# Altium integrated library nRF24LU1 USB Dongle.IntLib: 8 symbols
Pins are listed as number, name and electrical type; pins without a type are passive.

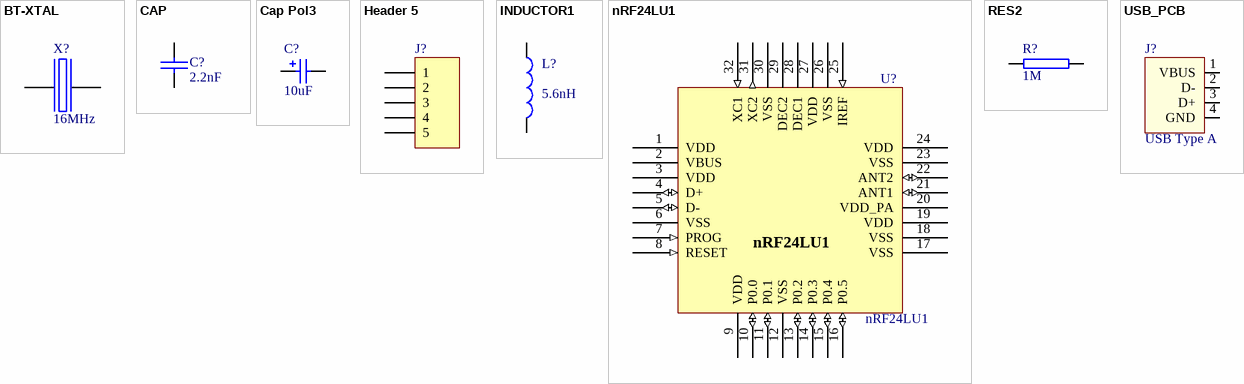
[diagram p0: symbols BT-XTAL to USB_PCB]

## BT-XTAL
designator X?, comment value 16MHz  (hidden comment: FA-20H 16MHz, CL=12pF)
footprint BT-XTAL 2520 (TSX-2520)
pins: 1 inp, 2 GND hidden to GND, 3 out, 4 GND hidden to GND

## CAP
designator C?, comment value 2.2nF  (hidden comment: X7R +/-10%)
Part Field 1: 0402
footprint 0402s
pins: 1, 2

## Cap Pol3
designator C?, comment value 10uF  (hidden comment: X5R +/-10%, 6.3v)
Polarized Capacitor (Surface Mount)
footprint 0603s
footprint C1206 (Chip Capacitor; Body 3.2 x 1.6 mm (LxW typ))
footprint 1825 (Chip Capacitor; Body 4.5 x 6.4 mm (LxW typ))
footprint C2225 (Chip Capacitor; Body 5.6 x 6.4 mm (LxW typ))
footprint 2220 (Chip Capacitor; Body 5.7 x 5.0 mm (LxW typ))
simulation model CAP (Capacitor)
signal-integrity model Cap Pol
pins: 1, 2
1 alternate drawing of the same symbol

## Header 5
designator J?, comment Digikey 455-1791-1-ND  (value not drawn)
Header, 5-Pin; Value: JST BM05B-SRSS-TB
footprint SH-5
signal-integrity model Connector
pins: 1, 2, 3, 4, 5

## INDUCTOR1
designator L?, comment value 5.6nH  (hidden comment: Chip Inductor +/-5%)
Part Field 1: 0402
footprint 0402s
pins: 1, 2

## nRF24LU1
designator U?
2.4GHz Transceiver with USB
footprint QFN32L/5x5
pins: 1 VDD (power) "Power supply (+3.3V DC) for de-coupling purposes", 2 VBUS (power) "USB power connection", 3 VDD (power) "Power supply (+3.3V DC) for de-coupling purposes", 4 D+ (io) "USB data +", 5 D- (io) "USB data -", 6 VSS (power) "Ground (0V)", 7 PROG (in) "Reserved for programming the flash", 8 RESET (in) "Reset for microcontroller, active low", 9 VDD (power) "Power supply (+3.3V DC) for de-coupling purposes", 10 P0.0 (io) "General purpose data Port 0, bit 0", 11 P0.1 (io) "General purpose data Port 0, bit 1", 12 VSS (power) "Ground (0V)", 13 P0.2 (io) "General purpose data Port 0, bit 2", 14 P0.3 (io) "General purpose data Port 0, bit 3", 15 P0.4 (io) "General purpose data Port 0, bit 4", 16 P0.5 (io) "General purpose data Port 0, bit 5", 17 VSS (power) "Ground (0V)", 18 VSS (power) "GND", 19 VDD (power) "Power supply (+3.3V DC) for de-coupling purposes", 20 VDD_PA (power) "Power Supply (+1.8V) to Power Amplifier", 21 ANT1 (io) "Antenna connection 1", 22 ANT2 (io) "Antenna connection 2", 23 VSS (power) "Ground (0V)", 24 VDD (power) "Power supply (+3.3V DC) for de-coupling purposes", 25 IREF (in) "Reference current", 26 VSS (power) "Ground (0V)", 27 VDD (power) "Power supply (+3.3V DC) for de-coupling purposes", 28 DEC1 (power) "Positive Digital Supply output for de-coupling purposes", 29 DEC2 (power) "Positive Digital Supply output for de-coupling purposes", 30 VSS (power) "Ground (0V)", 31 XC2 (out) "Crystal connection 2", 32 XC1 (in) "Crystal connection 1"

## RES2
designator R?, comment value 1M  (hidden comment: 5%)
Part Field 1: 0402
footprint 0402s
pins: 1, 2

## USB_PCB
designator J?, comment USB Type A
Value: Molex 48037-1000
footprint ACIN USD SMD
pins: 1 VBUS, 2 D-, 3 D+, 4 GND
